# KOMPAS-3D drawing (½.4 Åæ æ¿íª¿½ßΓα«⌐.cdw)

Views: Вид 1
Referenced files in C:\Program Files\ASCON\KOMPAS-3D V10\Sys\: SPDS.lcs, Graphic.lcs
Referenced files in \\F-server\проектирование\Проекты\РЗА и ПА Тюменские РС\4. Проект\ЭП\Туринская\Рабочая документация\: план располодения оборудования на ПС.cdw
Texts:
  Текст на чертеже
  Размерные надписи
  Шероховатость
  Линия-выноска #1
  Линия-выноска #2
  Линия-выноска #3
  Отклонения формы и база
  Заголовок таблицы
  Ячейка таблицы
  Стрелка вида
  Обозначение изменения
  Фигурная скобка
  Номер узла
  Марка координационной оси
  VRCB
  Выносная надпись
  Обозначение узла
  Марка/позиционное обозначение с линией-выноской
  Марка/позиционное обозначение на линии
  Марка/позиционное обозначение без линии-выноски
  Лит-Масса-Масштаб
  Материал-Предприятие
  Title Specification
  Body Specification ( left align )
  Body Specificaton ( centered )
  Без имени
  Normal
  heading 1
  Знак Знак Знак Знак Знак Знак
  Verdana
  Body Text
  MS Sans Serif
  Txt
  Simplex
  TXT
  Обычный
  Термин
  Список определений
  Адрес
  Цитаты
  Форматированный
  Courier New
  Z-конец формы
  Z-начало формы
  Additional DXF text style 0
  Абзац Знак
  Body Text 3
  Title
  ТекстШаг1
  Шрифт 2.5
  Заголовки
  txt
  heading 2
  AGOpus
  footer
  Денис
  RUSTXT
  Обычный (веб)
  ООббыыччнныыйй
  Definition Term
  Definition List
  Address
  Blockquote
  Preformatted
  z-Bottom of Form
  z-Top of Form
  header
  NormalParagraphStyle
  ссылки
  Подпись в квадратике
  табл
  цепи
  Маркировка
  клеммы, контакты
  тексты табл
  Тексты. 3,2
  ЗОНА_привяз
  текст переноса
  ТТееррммиинн
  ССппииссоокк ооппррееддееллеенниийй
  ААддрреесс
  ЦЦииттааттыы
  ФФооррммааттиирроовваанннныыйй
  Z-ккооннеецц ффооррммыы
  Z-ннааччааллоо ффооррммыы
  GOST 2.304 type A
  rustxt
  heading 8
  heading 3
  heading 6
  heading 7
  russ
  heading 4
  heading 5
  heading 9
  HeliosLight
  Pa3
  Pa1
  Три с половиной
  style2
  Table Contents
  Table Heading
  ГОСТ_МНЕ
  ESK - Обозначение
  маркировка
  ISOCP
  ROMANS
  SIMPLEX
  Текст 3,5
  Tahoma
  CNBNDG+TimesNewRoman
  Subtitle
  FR5
  подписи
  Аппараты
  Ссылки
  Состав чартежа
  ячейка табл.
  Пояснения
  Клеммник текст
  .07 RGB_0_0_0 i0b0u0
  CM12
  romans
  текст табл
  Body Text Indent 3
  Основной текст с отступом 3
  gif
  Пояснения 2
  romanc
  eskd1
  Pa15
  Pa18
  ISOCPEUR
  CC С?т?и?л?ь? П?о? ц?е?н?т?р?у?
  Normal (Web)
  ошиноска 110
  лотки
  поз
  Поз.
  Перечень элементов
  Кол.
  ед., кг
  Приме-
  чание
  Трансформатор силовой маслянный
  с 2 комплектами заземляющих ножей
  Разъединитель трёхполюсный 110кВ
  Трансформатор трехфазный
  двухобмоточный масляный
  ТМ-400/10-0,4
  Выключатель маслянный колонковый
  ВМТ-110Б-25/1250 УХЛ1
  Выключатель элегазовый 110 кВ
  ТРНДЦН-25000/110 У1
  трехобмоточный
  РДЗ 2-110/1000 У1
  с 1 комплектом заземляющих ножей
  РДЗ 1-110/1000 У1
  сущ.
  EXLIM R 120
  Ограничитель перенапряжения 110 кВ
  SGF 123
  Трансформатор тока 110 кВ
  ТФЗМ-110Б-IV У1
  Трансформатор напряжения 110 кВ
  НКФ-110-83 У1
  ВЧ-заградитель 110 кВ
  ВЗ-630
  Конденсатор связи 110 кВ
  СМПВ-110/ 3 -6,4
  Изолятор опорный 110 кВ
  Фильтр присоединения 110кВ
  ФП 6400
  Разъединитель РВО-10
  РВО-10/400
  Разъединитель однополюсный 10 кВ
  проект.
  ТСН 1
  ТСН 2
  Экспликация зданий и сооружений
  Номер
  на плане
  Постоянные здания и сооружения
  ОПУ
  ЗРУ 10 кВ
  Трансформатор 1Т, маслоприемник
  Трансформатор 2Т, маслоприемник
  Существующее
  Существующий
  Временные здания и сооружения
  III
  Вагон-дом для кратковременного отдых рабочих
  Уборная
  Дизельная электростанция
  Контейнеры для ТБО (0,75м 3 ) и жидких хоз.-быт.стоков(1м 3 )
  «Екатерина» 9,0х3,0
  Туалетная кабина "Люкс"
  ОАО ПКТИпромстрой
  АДС 45-Т400 РЯ
  - предупреждающий знак
  "Опасно. Возможно падение груза"
  "Опасность поражения электрическим током"
  - стоянка крана во время производства работ
  - стенд с противопожарным инвентарем
  - знак ограничения поворота стрелы
  - опасная зона работы при перемещении грузов
  Условные обозначения:
  Примечания:
  1. Для нужд строительства (размещение задействованного в строительстве персонала, обеспечение электроэнергией) использовать временные мобильные
  инвентарные здания;
  2. При выполнении всех строительно-монтажных работ на площадке необходимо руководствоваться требованиями СНиП 12-03-2001 "Безопасность труда в
  строительстве. Общие требования",  СНиП 12-04-2002 "Безопасность труда в строительстве. Строительное производство", а также  ПОТ-РМ-016-2001/
  РД 153-34.0-03.150-00 "Межотраслевые правила по охране труда (правила безопасности) при эксплуатации электроустановок";
  3. Наружное освещение строительной площадки осуществляется за счет существующего освещения;
  4. Под временные сооружения (поз. II, III и IV) устраивается площадка из дорожных плит ПД 60-20 на  щебеночном основании толщиной 15см;
  5. На период строительства для электроснабжения временных зданий и сооружений использовать дизельную электростанцию. Прокладку  кабеля от
  дизельной электростанции до вагончиков выполнить в воздушном исполнении в гофрированной трубе диаметром 30 мм, на вагончиках кабель закрепить
  скобами. Щиток временного электроснабжения навесить на стенку вагона-дома для отдыха рабочих;
  6. При выполнении монтажных работ использовать инвентарные лестницы и леса;
  7. На паспорте-стенде строительного объекта  должен быть план пожарной защиты с нанесенными строящимися и вспомогательными зданиями и
  сооружениями, въездами, подъездами, местонахождениями водоисточников, средств пожаротушения и связи (согласно ППБ-01-03 п.575);
  8. Тонкой линией изображено существующее оборудование, замена которого проектом не предусматривается, утолщенной - вновь устанавливаемое оборудование.
  9. Грузовысотные характеристики КМУ ИНМАН ИМ-150 см. 16/01-ПОС,л.7.
  - паспорт-стенд строительного
  объекта
  - запрещающий знак ограничения
  скорости движения автомобиля
  КМУ ИНМАН ИМ-150
  K5LT_BASIC_RGB_0_0_255_THICK_0.6
  POLYLINE_STYLE_0.18_RGB_128_64_0
  POLYLINE_STYLE_0.18_RGB_0_0_0
  POLYLINE_STYLE_0.20_RGB_0_0_0
  POLYLINE_STYLE_0.18_RGB_0_80_80
  Стили документа
  Бортовой автомобиль КамАЗ 43114-027-02
  АТ ППР#010#0104
  ГИП
  Н.контр.
  Гл.спец.
  Провер.
  Разраб.
  Перезавод ВЛ на ПС Тюмень. Реконструкция устройств
  РЗ и ПА на обратных концах отходящих ВЛ,
  ВОЛС Тюменского ТПО
  ПС 110/10 кВ Сибжилстрой
  Матвеев
  Ромин
  Шашерин
  Королева
  Строительный генеральный план
  Ведомость эскизного проекта
Dimensions and other numbers on the sheet: 16/01-ПОС; 7; 2,5; 1,8; 2.5; 3,2_; 3.5; 3,2; 2,5 (контакты, клеммы); 3,2 (надписи); 3,2 (Зоны); 5; 2,5_01; 2,5_3; 3,5_01; 3,5_tabl; 5_заголовок; 2,3_; 3,2_зона не привяз; 3,5; 3.2 маркировка; 3,2 элементы; 3,2 линия; 3,2 таблица; 2,5 грязносинь; 2.5 курсив; 2.5_Э5_надписи; 2.5_Э5_ссылки; 2.5_кабель; 3.2; 2.5 надписи; 3 и 5; 5,0_белый_подчёркнутый; 3.2 фиол; 3.2 (текст); 0 i0b0u0; 1; 2; 3; 4; 6; 145 РМ 40-20; 14; 11; 21; 4000; 5000; 3000; 4500; 4900; 8100; 11000; 5100; 10000; 7500; 6000; 14000; 7000; 1000; 3700; 8; 9; 10; 12; 13; 33; 16; 17; 18; 19; 20; 15; 50; 105000; 157000; 22000; 7,5; 5,5; 13,2; 11,2; 05.13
